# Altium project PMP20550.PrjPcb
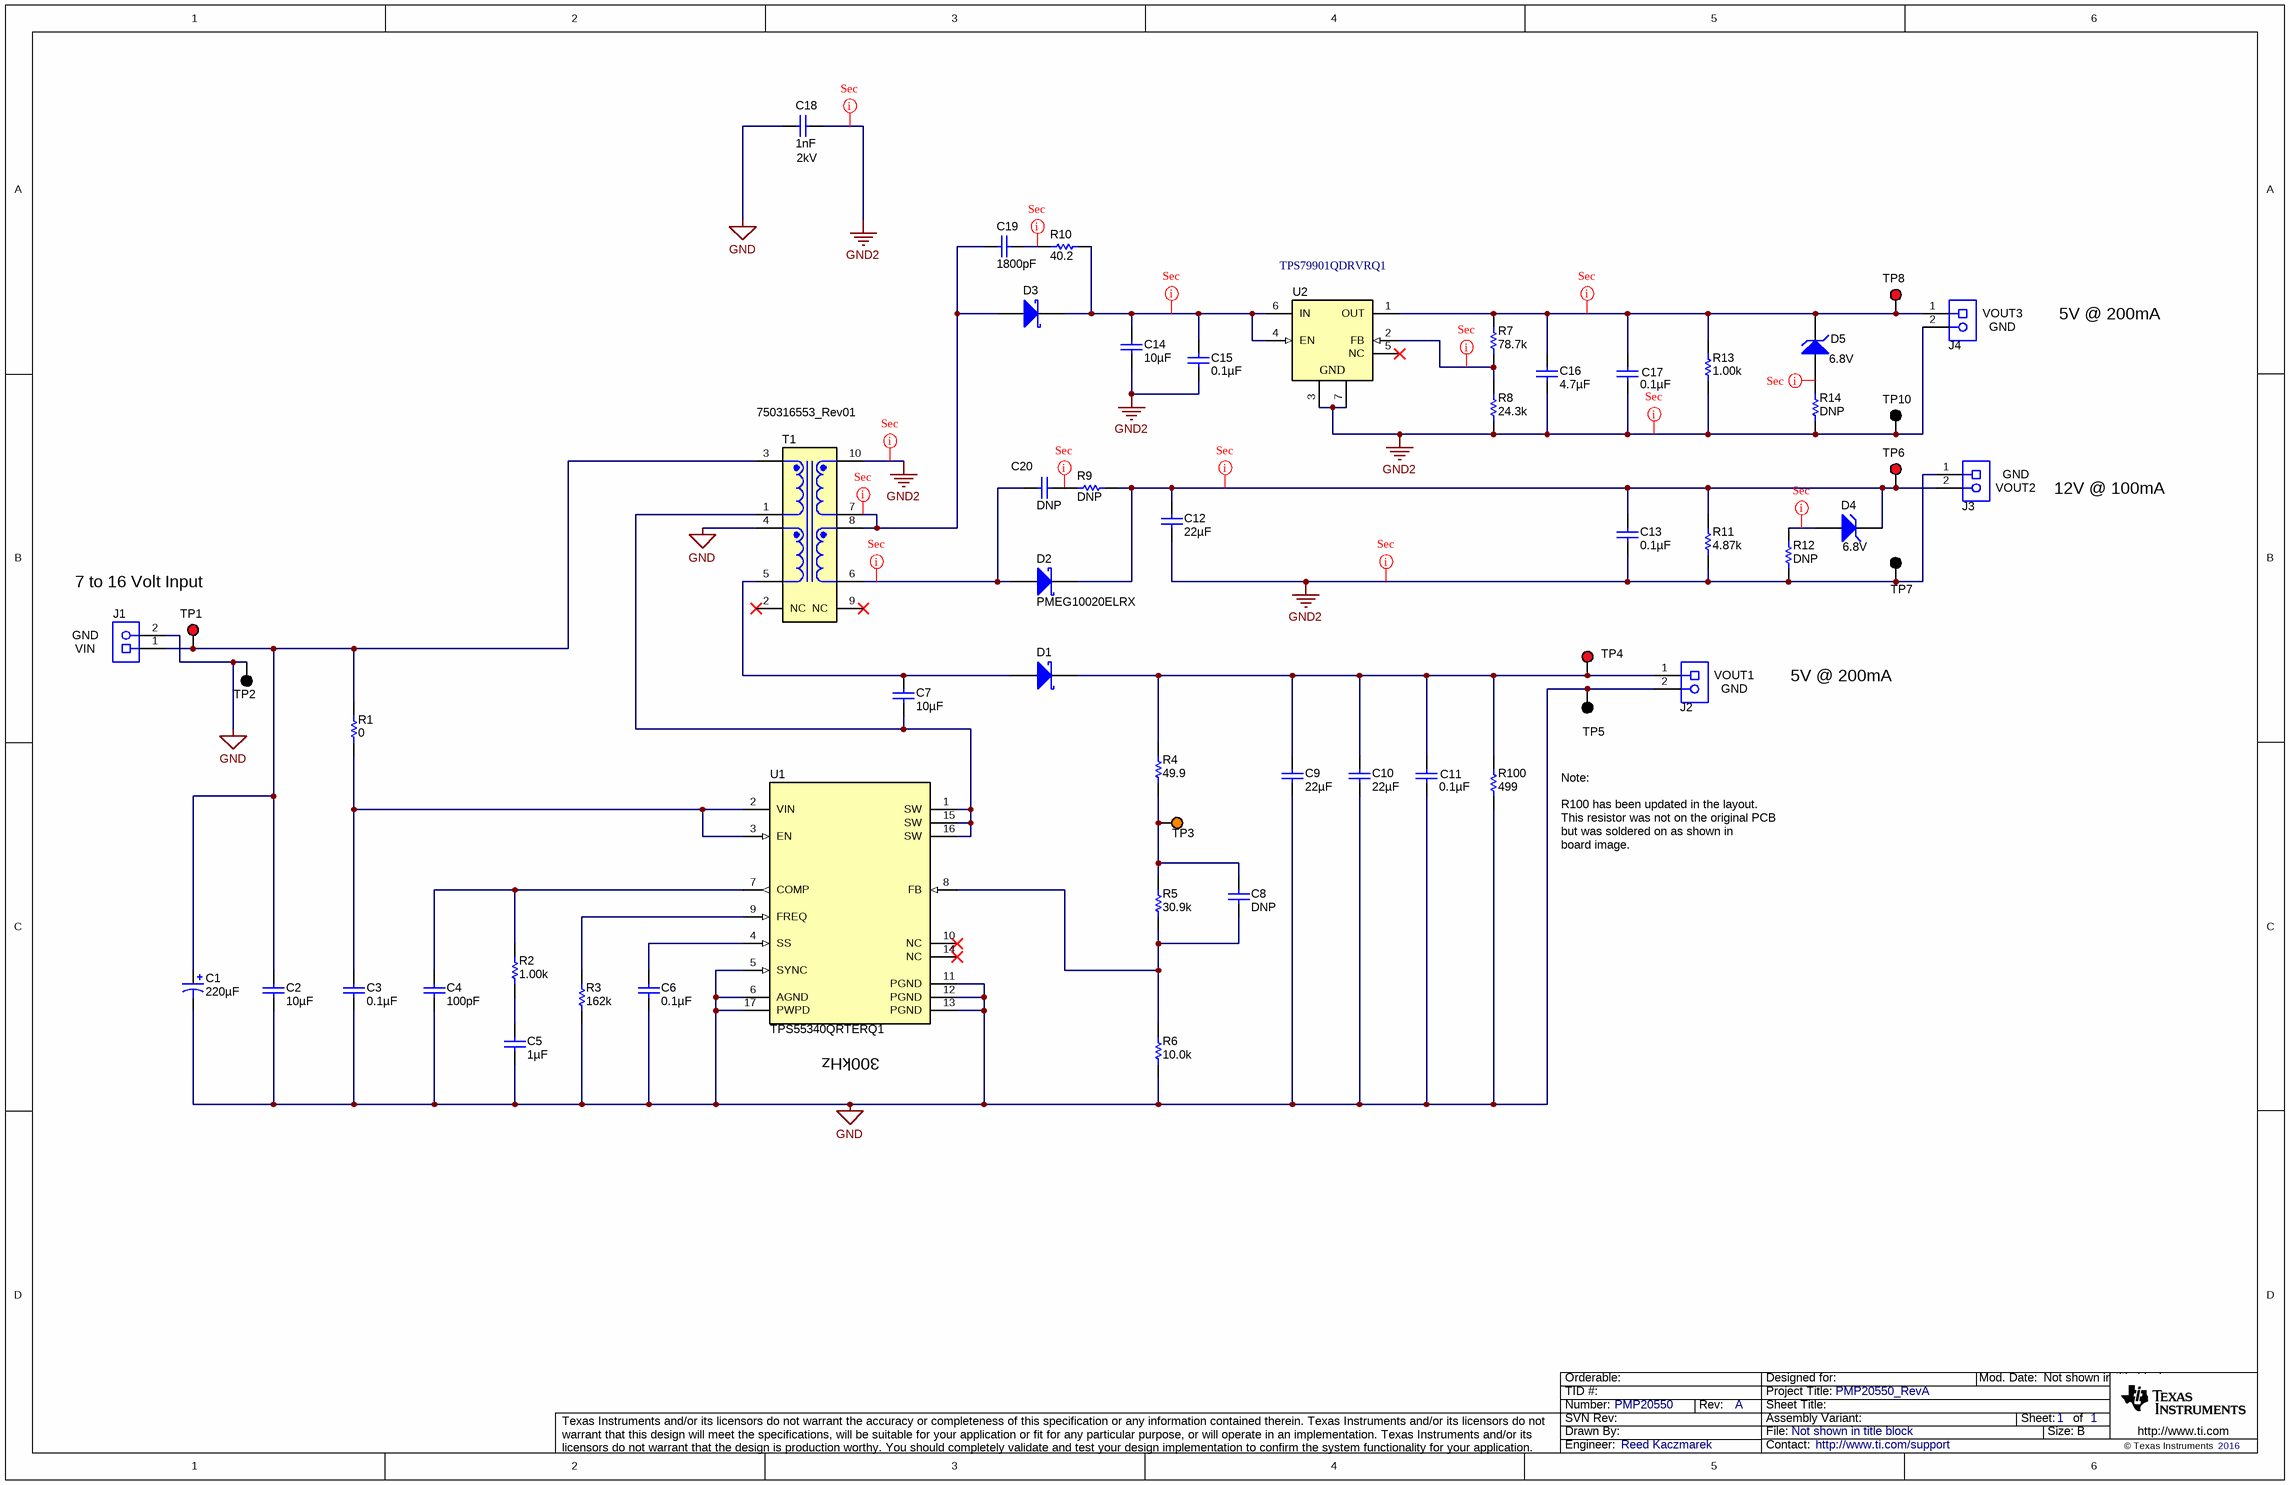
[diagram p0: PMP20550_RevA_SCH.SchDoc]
TechSupport: http://www.ti.com/support; SCH_Rev: A; PRJ_Title: PMP20550_RevA; PRJ_Number: PMP20550; PRJ_Engineer: Reed Kaczmarek; PCB_Rev: A; CopyrightYear: 2016
1 sheet, 56 parts. Net scope: global (net labels, ports and power ports of the same name join across sheets).
Board file: PMP20550_RevA.PcbDoc

## Sheet PMP20550_RevA_SCH.SchDoc
size 431 x 279 mm; Date: Not shown in title block; ApprovedBy: Not shown in title block; CheckedBy: Not shown in title block; Author: Not shown in title block; CompanyName: Not shown in title block; Engineer: Not shown in title block; Organization: Not shown in title block; Address1: Not shown in title block; Address2: Not shown in title block; Address3: Not shown in title block; Address4: Not shown in title block; DocumentNumber: 1; Revision: Use project parameter SCH_Rev; SheetNumber: 1; SheetTotal: 1; PageSetup: Record=PageOptions¦CenterHorizontal=True¦CenterVertical=True¦PrintScale=1.00¦XCorrection=1.00¦YCorrection=1.00¦PrintKind=0¦BorderSize=5000000¦LeftOffset=0¦BottomOffset=0¦Orientation=2¦PaperLength=1000¦PaperWidth=1000¦Scale=100¦PaperSource=15¦PrintQuality=600¦MediaType=1¦DitherType=10¦PaperKind=Letter¦PrintScaleMode=1

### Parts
C1  ValueDisplayed: 220µF  [SM_RADIAL_G]  (hidden comment: EEE-FC1V221P)
C2  ValueDisplayed: 10µF  [1206]  (hidden comment: GMK316AB7106KL)
C3  ValueDisplayed: 0.1µF  [0603]  (hidden comment: C1608X7R1E104K080AA)
C4  ValueDisplayed: 100pF  [0603]  (hidden comment: CGA3E2NP01H101J080AA)
C5  ValueDisplayed: 1µF  [0603]  (hidden comment: UMK107AB7105KA-T)
C6  ValueDisplayed: 0.1µF  [0603]  (hidden comment: C1608X7R1E104K080AA)
C7  ValueDisplayed: 10µF  [0805_HV]  (hidden comment: GRM21BR6YA106KE43L)
C8  ValueDisplayed: DNP  [0402]  (hidden comment: GRM1555C1H201JA01D)
C9  ValueDisplayed: 22µF  [0805_HV]  (hidden comment: GRM21BZ71A226ME15L)
C10  ValueDisplayed: 22µF  [0805_HV]  (hidden comment: GRM21BZ71A226ME15L)
C11  ValueDisplayed: 0.1µF  [0603]  (hidden comment: C0603X104K8RACTU)
C12  ValueDisplayed: 22µF  [1210_280]  (hidden comment: 12103D226MAT2A)
C13  ValueDisplayed: 0.1µF  [0603]  (hidden comment: GRM188R71H104KA93D)
C14  ValueDisplayed: 10µF  [0603]  (hidden comment: GRM188Z71A106MA73D)
C15  ValueDisplayed: 0.1µF  [0603]  (hidden comment: C1608X7R1E104K080AA)
C16  ValueDisplayed: 4.7µF  [0805_HV]  (hidden comment: C2012X7R1E474K125AA)
C17  ValueDisplayed: 0.1µF  [0603]  (hidden comment: C0603X104K8RACTU)
C18  ValueDisplayed: 1nF  Value2: 2kV  [1812]  (hidden comment: GR443QR73D102KW01L)
C19  ValueDisplayed: 1800pF  [0603]  (hidden comment: GRM1885C1H182JA01D)
C20  ValueDisplayed: DNP  [0603]  (hidden comment: GRM1885C1H111JA01D)
D1  PMEG2020EJ,115  [SOD-323F]  (value not drawn)
D2  PMEG10020ELRX  [SOD-123W]
D3  PMEG2020EJ,115  [SOD-323F]  (value not drawn)
D4  value 6.8V  [SOD-323]  (hidden comment: MMSZ5235BS-7-F)
D5  value 6.8V  [SOD-323]  (hidden comment: MMSZ5235BS-7-F)
J1  1984617  [Phoenix_1984617]  (value not drawn)
J2  1984617  [Phoenix_1984617]  (value not drawn)
J3  1984617  [Phoenix_1984617]  (value not drawn)
J4  1984617  [Phoenix_1984617]  (value not drawn)
R1  ValueDisplayed: 0  [0603]  (hidden comment: ERJ-3GEY0R00V)
R2  ValueDisplayed: 1.00k  [0603]  (hidden comment: RT0603BRB071KL)
R3  ValueDisplayed: 162k  [0603]  (hidden comment: CRCW0603162KFKEA)
R4  ValueDisplayed: 49.9  [0402]  (hidden comment: ERJ-2RKF49R9X)
R5  ValueDisplayed: 30.9k  [0603]  (hidden comment: CRCW060330K9FKEA)
R6  ValueDisplayed: 10.0k  [0402]  (hidden comment: ERJ-2RKF1002X)
R7  ValueDisplayed: 78.7k  [0603]  (hidden comment: RC0603FR-0778K7L)
R8  ValueDisplayed: 24.3k  [0603]  (hidden comment: RT0603DRE0724K3L)
R9  ValueDisplayed: DNP  [0603]  (hidden comment: CPF0603B1K62E)
R10  ValueDisplayed: 40.2  [0603]  (hidden comment: CRCW060340R2FKEA)
R11  ValueDisplayed: 4.87k  [0805_HV]  (hidden comment: ERJ-6ENF4871V)
R12  ValueDisplayed: DNP  [0603]  (hidden comment: CPF0603B1K62E)
R13  ValueDisplayed: 1.00k  [0805_HV]  (hidden comment: RT0805BRD071KL)
R14  ValueDisplayed: DNP  [0603]  (hidden comment: CPF0603B1K62E)
R100  ValueDisplayed: 499  [0805_HV]  (hidden comment: RT0805BRD07499RL)
T1  750316553_Rev01  [Wurth_750316553]
TP1  5000  [Keystone5000]  (value not drawn)
TP2  5001  [Keystone5001]  (value not drawn)
TP3  5003  [Keystone5003]  (value not drawn)
TP4  VBUS  [Keystone5000]  (value not drawn)
TP5  5001  [Keystone5001]  (value not drawn)
TP6  5000  [Keystone5000]  (value not drawn)
TP7  5001  [Keystone5001]  (value not drawn)
TP8  5000  [Keystone5000]  (value not drawn)
TP10  5001  [Keystone5001]  (value not drawn)
U1  TPS55340QRTERQ1  [RTE0016C]
U2  TPS79901QDRVRQ1  [DRV0006A]

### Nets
GND: C1.2(-) C2.2 C3.2 C4.2 C5.2 C6.2 C9.2 C10.2 C11.2 C18.2 J1.2 J2.2 R3.1 R6.1 R100.1 T1.4 TP2.1 TP5.1 U1.5(SYNC) U1.6(AGND) U1.11(PGND) U1.12(PGND) U1.13(PGND) U1.17(PWPD)
GND2: C12.2 C13.2 C14.2 C15.2 C16.2 C17.2 C18.1 J3.1 J4.2 R8.1 R11.1 R12.2 R13.1 R14.2 T1.10 TP7.1 TP10.1 U2.3(GND) U2.7(GND)
NetC1_1: C1.1(+) C2.1 J1.1 R1.2 T1.3 TP1.1
NetC3_1: C3.1 R1.1 U1.2(VIN) U1.3(EN)
NetC4_1: C4.1 R2.2 U1.7(COMP)
NetC5_1: C5.1 R2.1
NetC6_1: C6.1 U1.4(SS)
NetC7_1: C7.1 D1.2(A) T1.5
NetC7_2: C7.2 T1.1 U1.1(SW) U1.15(SW) U1.16(SW)
NetC8_1: C8.1 R4.1 R5.2 TP3.1
NetC8_2: C8.2 R5.1 R6.2 U1.8(FB)
NetC9_1: C9.1 C10.1 C11.1 D1.1(K) J2.1 R4.2 R100.2 TP4.1
NetC12_1: C12.1 C13.1 D2.1(K) D4.1(K) J3.2 R9.1 R11.2 TP6.1
NetC14_1: C14.1 C15.1 D3.1(K) R10.2 U2.4(EN) U2.6(IN)
NetC16_1: C16.1 C17.1 D5.1(K) J4.1 R7.2 R13.2 TP8.1 U2.1(OUT)
NetC19_1: C19.1 R10.1
NetC19_2: C19.2 D3.2(A) T1.7 T1.8
NetC20_1: C20.1 R9.2
NetC20_2: C20.2 D2.2(A) T1.6
NetD4_2: D4.2(A) R12.1
NetD5_2: D5.2(A) R14.1
NetR3_2: R3.2 U1.9(FREQ)
NetR7_1: R7.1 R8.2 U2.2(FB)

Not connected (* = marked no-connect by the designer): T1 2(NC)* 9(NC)*; U1 10(NC)* 14(NC)*; U2 5(NC)*

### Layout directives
net class Undefined: GND2, NetC12_1, NetC14_1, NetC16_1, NetC19_1, NetC19_2, NetC20_1, NetC20_2, NetD4_2, NetD5_2, NetR7_1

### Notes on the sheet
- (near J4) VOUT3
- (near J4) GND
- 5V @ 200mA
- (near J3) VOUT2
- (near J3) GND
- 12V @ 100mA
- (near J1) GND
- 7 to 16 Volt Input
- (near J1) VIN
- (near J2) VOUT1
- (near J2) GND
- Note:
  R100 has been updated in the layout.
  This resistor was not on the original PCB
  but was soldered on as shown in
  board image.
- (near U1) 300kHz

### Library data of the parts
C1 = EEE-FC1V221P: CAP, AL, 220 µF, 35 V, +/- 20%, 0.15 ohm, SMD; Manufacturer: Panasonic; Polarized: Y; CompType: Capacitor; Value: 220uF; U/M: EA; Cap_F: 0.00022; Tolerance_%: 20; VDC_V: 35; Value2: 35V; ESR_ohm: 0.15; IRMS_A: 0.67; TaMin_C: -40; TaMax_C: 105; Cap_Case: G; SizeAreaWB_mm2: 172.2; SizeArea_mm2: 123.6; SizeX_mm: 12; SizeY_mm: 10.3; SizeZ_mm: 10.2; AEC Category: Q200
C2 = GMK316AB7106KL: CAP, CERM, 10 µF, 35 V, +/- 10%, X7R, 1206; Manufacturer: Taiyo Yuden; Polarized: N; CompType: Capacitor; Value: 10uF; U/M: EA; Cap_F: 0.00001; Tolerance_%: 10; Value1: Unknown; VDC_V: 35; Value2: 35V; TaMin_C: -55; TaMax_C: 125; SizeArea_mm2: 5.12; SizeAreaWB_mm2: 10.92; SizeX_mm: 3.2; SizeY_mm: 1.6; SizeZ_mm: 1.35; AEC Category: Q200
C3 C6 C15 = C1608X7R1E104K080AA: CAP, CERM, 0.1 µF, 25 V, +/- 10%, X7R, 0603; Manufacturer: TDK; Polarized: N; CompType: Capacitor; Value: 0.1uF; U/M: EA; Cap_F: 0.0000001; Tolerance_%: 10; Value1: Unknown; VDC_V: 25; Value2: 25V; TaMin_C: -55; TaMax_C: 125; SizeArea_mm2: 1.28; SizeAreaWB_mm2: 4.68; SizeX_mm: 1.6; SizeY_mm: 0.8; SizeZ_mm: 1; AEC Category: Q200
C4 = CGA3E2NP01H101J080AA: CAP, CERM, 100 pF, 50 V, +/- 5%, C0G/NP0, AEC-Q200 Grade 0, 0603; Manufacturer: TDK; Polarized: N; CompType: Capacitor; Value: 100pF; U/M: EA; Cap_F: 0.0000000001; Tolerance_%: 5; Value1: Unknown; VDC_V: 50; Value2: 50V; TaMin_C: -55; TaMax_C: 150; SizeArea_mm2: 1.28; SizeAreaWB_mm2: 4.68; SizeX_mm: 1.6; SizeY_mm: 0.8; SizeZ_mm: 1; AEC Category: Q200; AEC Qualified: Y; AEC Grade: 0
C5 = UMK107AB7105KA-T: CAP, CERM, 1 µF, 50 V, +/- 10%, X7R, 0603; Manufacturer: Taiyo Yuden; Polarized: N; CompType: Capacitor; Value: 1uF; U/M: EA; Cap_F: 0.000001; Tolerance_%: 10; Value1: Unknown; VDC_V: 50; Value2: 50V; TaMin_C: -55; TaMax_C: 125; SizeArea_mm2: 1.28; SizeAreaWB_mm2: 4.68; SizeX_mm: 1.6; SizeY_mm: 0.8; SizeZ_mm: 1; AEC Category: Q200
C7 = GRM21BR6YA106KE43L: CAP, CERM, 10 µF, 35 V, +/- 10%, X5R, 0805; Manufacturer: MuRata; Polarized: N; CompType: Capacitor; Value: 10uF; U/M: EA; Cap_F: 0.00001; Tolerance_%: 10; Value1: Unknown; VDC_V: 35; Value2: 35V; TaMin_C: -55; TaMax_C: 85; Cap_Case: 0805; SizeArea_mm2: 2.5; SizeAreaWB_mm2: 6.75; SizeX_mm: 2; SizeY_mm: 1.25; SizeZ_mm: 1.45; AEC Category: Q200
C8 = GRM1555C1H201JA01D: CAP, CERM, 200 pF, 50 V, +/- 5%, C0G/NP0, 0402; Manufacturer: MuRata; Polarized: N; CompType: Capacitor; Value: 200pF; U/M: EA; Cap_F: 0.0000000002; Tolerance_%: 5; Value1: Unknown; VDC_V: 50; Value2: 50V; TaMin_C: -55; TaMax_C: 125; SizeArea_mm2: 0.5; SizeAreaWB_mm2: 3; SizeX_mm: 1; SizeZ_mm: 0.6; AEC Category: Q200
C9 C10 = GRM21BZ71A226ME15L: CAP, CERM, 22 µF, 10 V, +/- 20%, X7R, 0805; Manufacturer: MuRata; Polarized: N; CompType: Capacitor; Value: 22uF; U/M: EA; Cap_F: 0.000022; Tolerance_%: 20; Value1: Unknown; VDC_V: 10; Value2: 10V; TaMin_C: -55; TaMax_C: 125; Cap_Case: 0805; SizeArea_mm2: 2.5; SizeAreaWB_mm2: 6.75; SizeX_mm: 2; SizeY_mm: 1.25; SizeZ_mm: 1.45; AEC Category: Q200
C11 C17 = C0603X104K8RACTU: CAP, CERM, 0.1 µF, 10 V, +/- 10%, X7R, 0603; Manufacturer: Kemet; Polarized: N; CompType: Capacitor; Value: 0.1uF; U/M: EA; Cap_F: 0.0000001; Tolerance_%: 10; Value1: Unknown; Value2: 10V; TaMin_C: -55; TaMax_C: 125; SizeArea_mm2: 1.28; SizeAreaWB_mm2: 4.68; SizeX_mm: 1.6; SizeY_mm: 0.8; SizeZ_mm: 1; AEC Category: Q200
C12 = 12103D226MAT2A: CAP, CERM, 22 µF, 25 V, +/- 20%, X5R, 1210; Manufacturer: AVX; Polarized: N; CompType: Capacitor; Value: 22uF; U/M: EA; Cap_F: 0.000022; Tolerance_%: 20; Value1: Unknown; VDC_V: 25; Value2: 25V; TaMin_C: -55; TaMax_C: 85; Cap_Case: 1210; SizeArea_mm2: 8; SizeAreaWB_mm2: 14.7; SizeX_mm: 3.2; SizeY_mm: 2.5; SizeZ_mm: 2.8; AEC Category: Q200
C13 = GRM188R71H104KA93D: CAP, CERM, 0.1 µF, 50 V, +/- 10%, X7R, 0603; Manufacturer: MuRata; Polarized: N; CompType: Capacitor; Value: 0.1uF; U/M: EA; Cap_F: 0.0000001; Tolerance_%: 10; Value1: Unknown; VDC_V: 50; Value2: 50V; TaMin_C: -55; TaMax_C: 125; SizeArea_mm2: 1.28; SizeAreaWB_mm2: 4.68; SizeX_mm: 1.6; SizeY_mm: 0.8; SizeZ_mm: 1; AEC Category: Q200
C14 = GRM188Z71A106MA73D: CAP, CERM, 10 µF, 10 V, +/- 20%, X7R, 0603; Manufacturer: MuRata; Polarized: N; CompType: Capacitor; Value: 10uF; U/M: EA; Cap_F: 0.00001; Tolerance_%: 20; Value1: Unknown; VDC_V: 10; Value2: 10V; TaMin_C: -55; TaMax_C: 125; SizeArea_mm2: 1.28; SizeAreaWB_mm2: 4.68; SizeX_mm: 1.6; SizeY_mm: 0.8; SizeZ_mm: 1; AEC Category: Q200
C16 = C2012X7R1E474K125AA: CAP, CERM, 4.7 µF, 25 V, +/- 10%, X7R, 0805; Manufacturer: TDK; Polarized: N; CompType: Capacitor; Value: 4.7uF; U/M: EA; Cap_F: 0.0000047; Tolerance_%: 10; Value1: Unknown; VDC_V: 25; Value2: 25V; TaMin_C: -55; TaMax_C: 125; Cap_Case: 0805; SizeArea_mm2: 2.5; SizeAreaWB_mm2: 6.75; SizeX_mm: 2; SizeY_mm: 1.25; SizeZ_mm: 1.45; AEC Category: Q200
C18 = GR443QR73D102KW01L: CAP, CERM, 1000 pF, 2000 V, +/- 10%, X7R, 1812; Manufacturer: MuRata; Polarized: N; CompType: Capacitor; Value: 1000pF; U/M: EA; Cap_F: 0.000000001; Tolerance_%: 10; Value1: Unknown; VDC_V: 2000; TaMin_C: -55; TaMax_C: 125; SizeArea_mm2: 14.4; SizeAreaWB_mm2: 23.1; SizeX_mm: 4.5; SizeY_mm: 3.2; SizeZ_mm: 1.35; AEC Category: Q200
C19 = GRM1885C1H182JA01D: CAP, CERM, 1800 pF, 50 V, +/- 5%, C0G/NP0, 0603; Manufacturer: MuRata; Polarized: N; CompType: Capacitor; Value: 1800pF; U/M: EA; Cap_F: 0.0000000018; Tolerance_%: 5; Value1: Unknown; VDC_V: 50; Value2: 50V; TaMin_C: -55; TaMax_C: 125; SizeArea_mm2: 1.28; SizeAreaWB_mm2: 4.68; SizeX_mm: 1.6; SizeY_mm: 0.8; SizeZ_mm: 1; AEC Category: Q200
C20 = GRM1885C1H111JA01D: CAP, CERM, 110 pF, 50 V, +/- 5%, C0G/NP0, 0603; Manufacturer: MuRata; Polarized: N; CompType: Capacitor; Value: 110pF; U/M: EA; Cap_F: 0.00000000011; Tolerance_%: 5; Value1: Unknown; VDC_V: 50; Value2: 50V; TaMin_C: -55; TaMax_C: 125; SizeArea_mm2: 1.28; SizeAreaWB_mm2: 4.68; SizeX_mm: 1.6; SizeY_mm: 0.8; SizeZ_mm: 1; AEC Category: Q200
D1 D3 = PMEG2020EJ,115: Diode, Schottky, 20 V, 2 A, SOD-323F; Manufacturer: NXP Semiconductor; U/M: EA; Vf_V: 0.525; Value: 20V; Value1: 2A; Value2: 0.525V; Io_A: 2; Vr_V: 20; TJmax_C: 150; SizeAreaWB_mm2: 7.875; SizeArea_mm2: 3.125; SizeX_mm: 2.5; SizeY_mm: 1.25; SizeZ_mm: 0.8; AEC Category: Q101; AEC Qualified: N
D2 = PMEG10020ELRX: Diode, Schottky, 100 V, 2 A, AEC-Q101, SOD-123W; Manufacturer: NXP Semiconductor; U/M: EA; Vf_V: 0.83; Value: 100V; Value1: 2A; Value2: 0.83V; Io_A: 2; Vr_V: 100; TJmax_C: 175; SizeAreaWB_mm2: 12.15; SizeArea_mm2: 5.95; SizeX_mm: 3.5; SizeY_mm: 1.7; SizeZ_mm: 1; AEC Category: Q101; AEC Qualified: Y
D4 D5 = MMSZ5235BS-7-F: Diode, Zener, 6.8 V, 200 mW, SOD-323; Manufacturer: Diodes Inc.; SymbolCreator: a0412235; U/M: EA; Power_W: 0.2; Vz_V: 6.8; Value1: 0.2W; RJA_CperW: 350; SizeAreaWB_mm2: 8.695; SizeArea_mm2: 3.645; SizeX_mm: 2.7; SizeY_mm: 1.35; SizeZ_mm: 1; AEC Category: Q101
J1-J4 = 1984617: Terminal Block, 3.5mm, 2x1, TH; Manufacturer: Phoenix Contact; SymbolCreator: a0412235; Pitch_mm: 3.5; Gender: Female; Row_Count: 1; Current_A: 17.5; Voltage_V: 200; Cert_UL: Y
R1 = ERJ-3GEY0R00V: RES, 0, 5%, 0.1 W, 0603; Manufacturer: Panasonic; CompType: Resistor; Value: 0; Value_Code: 0000; Tolerance_%: 5; Power_W: 0.1; Value2: 0.1W; VDC_V: 50; TempCo: 600 ppm/C; SizeArea_mm2: 1.28; SizeX_mm: 1.6; SizeY_mm: 0.8; SizeZ_mm: 1; EIA_Code: E24; U/M: EA; AEC Category: Q200
R2 = RT0603BRB071KL: RES, 1.00 k, 0.1%, 0.1 W, 0603; Manufacturer: Yageo America; CompType: Resistor; Value: 1.00k; Res_ohm: 1000; Value_Code: 1k00; Tolerance_%: 0.1; Value2: 0.1W; VDC_V: 75; TempCo: 10 ppm/C; SizeArea_mm2: 1.28; SizeX_mm: 1.6; SizeY_mm: 0.8; SizeZ_mm: 1; EIA_Code: E192; U/M: EA; AEC Category: Q200; AEC Qualified: N
R3 = CRCW0603162KFKEA: RES, 162 k, 1%, 0.1 W, 0603; Manufacturer: Vishay-Dale; CompType: Resistor; Value: 162k; Res_ohm: 162000; Tolerance_%: 1; Power_W: 0.1; Value2: 0.1W; VDC_V: 75; TempCo: 100 ppm/C; SizeArea_mm2: 1.28; SizeX_mm: 1.6; SizeY_mm: 0.8; EIA_Code: E96; U/M: EA; AEC Category: Q200
R4 = ERJ-2RKF49R9X: RES, 49.9, 1%, 0.1 W, AEC-Q200 Grade 0, 0402; Manufacturer: Panasonic; CompType: Resistor; Value: 49.9; Value_Code: 49R9; Tolerance_%: 1; Power_W: 0.1; Value2: 0.1W; VDC_V: 50; TempCo: 100 ppm/C; SizeArea_mm2: 0.5; SizeZ_mm: 0.6; EIA_Code: E96; U/M: EA; AEC Category: Q200; AEC Qualified: Y; AEC Grade: 0
R5 = CRCW060330K9FKEA: RES, 30.9 k, 1%, 0.1 W, 0603; Manufacturer: Vishay-Dale; CompType: Resistor; Value: 30.9k; Res_ohm: 30900; Value_Code: 30k9; Tolerance_%: 1; Power_W: 0.1; Value2: 0.1W; VDC_V: 75; TempCo: 100 ppm/C; SizeArea_mm2: 1.28; SizeX_mm: 1.6; SizeY_mm: 0.8; EIA_Code: E96; U/M: EA; AEC Category: Q200
R6 = ERJ-2RKF1002X: RES, 10.0 k, 1%, 0.1 W, 0402; Manufacturer: Panasonic; CompType: Resistor; Value: 10.0k; Res_ohm: 10000; Value_Code: 10k0; Tolerance_%: 1; Power_W: 0.1; Value2: 0.1W; VDC_V: 50; TempCo: 100 ppm/C; SizeArea_mm2: 0.5; SizeZ_mm: 0.6; EIA_Code: E96; U/M: EA; AEC Category: Q200
R7 = RC0603FR-0778K7L: RES, 78.7 k, 1%, 0.1 W, 0603; Manufacturer: Yageo America; CompType: Resistor; Value: 78.7k; Res_ohm: 78700; Value_Code: 78k7; Tolerance_%: 1; Power_W: 0.1; Value2: 0.1W; VDC_V: 150; TempCo: 200 ppm/C; SizeArea_mm2: 1.28; SizeX_mm: 1.6; SizeY_mm: 0.8; EIA_Code: E96; U/M: EA; AEC Category: Q200
R8 = RT0603DRE0724K3L: RES, 24.3 k, 0.5%, 0.1 W, 0603; Manufacturer: Yageo America; CompType: Resistor; Value: 24.3k; Res_ohm: 24300; Value_Code: 24k3; Tolerance_%: 0.5; Power_W: 0.1; Value2: 0.1W; VDC_V: 75; TempCo: 50 ppm/C; SizeArea_mm2: 1.28; SizeX_mm: 1.6; SizeY_mm: 0.8; SizeZ_mm: 1; EIA_Code: E192; U/M: EA; AEC Category: Q200
R9 R12 R14 = CPF0603B1K62E: RES, 1.62 k, 0.1%, 0.063 W, 0603; Manufacturer: TE Connectivity; CompType: Resistor; Value: 1.62k; Res_ohm: 1620; Value_Code: 1k62; Tolerance_%: 0.1; Power_W: 0.063; Value2: 0.063W; VDC_V: 50; TempCo: 25 ppm/C; SizeArea_mm2: 1.28; SizeX_mm: 1.6; SizeY_mm: 0.8; SizeZ_mm: 1; EIA_Code: E192; U/M: EA; AEC Category: Q200
R10 = CRCW060340R2FKEA: RES, 40.2, 1%, 0.1 W, 0603; Manufacturer: Vishay-Dale; CompType: Resistor; Value: 40.2; Value_Code: 40R2; Tolerance_%: 1; Power_W: 0.1; Value2: 0.1W; VDC_V: 75; TempCo: 100 ppm/C; SizeArea_mm2: 1.28; SizeX_mm: 1.6; SizeY_mm: 0.8; EIA_Code: E96; U/M: EA; AEC Category: Q200
R11 = ERJ-6ENF4871V: RES, 4.87 k, 1%, 0.125 W, 0805; Manufacturer: Panasonic; CompType: Resistor; Value: 4.87k; Res_ohm: 4870; Value_Code: 4k87; Tolerance_%: 1; Power_W: 0.125; Value2: 0.125W; TempCo: 100 ppm/C; SizeArea_mm2: 2.5; SizeX_mm: 2; SizeY_mm: 1.25; SizeZ_mm: 1.45; EIA_Code: E96; U/M: EA; AEC Category: Q200
R13 = RT0805BRD071KL: RES, 1.00 k, 0.1%, 0.125 W, 0805; Manufacturer: Yageo America; CompType: Resistor; Value: 1.00k; Res_ohm: 1000; Value_Code: 1k00; Tolerance_%: 0.1; Power_W: 0.125; Value2: 0.125W; VDC_V: 150; TempCo: 25 ppm/C; SizeArea_mm2: 2.5; SizeX_mm: 2; SizeY_mm: 1.25; SizeZ_mm: 1.45; EIA_Code: E192; U/M: EA; AEC Category: Q200
R100 = RT0805BRD07499RL: RES, 499, 0.1%, 0.125 W, 0805; Manufacturer: Yageo America; CompType: Resistor; Value: 499; Value_Code: 499R; Tolerance_%: 0.1; Power_W: 0.125; Value2: 0.125W; VDC_V: 150; TempCo: 25 ppm/C; SizeArea_mm2: 2.5; SizeX_mm: 2; SizeY_mm: 1.25; SizeZ_mm: 1.45; EIA_Code: E192; U/M: EA; AEC Category: Q200
T1 = 750316553: Transformer, 52 uH, SMT; Manufacturer: Wurth Elektronik; SymbolCreator: Altium; Lp: 52; DCR_ohm: 0.065; Ns1toNp: 1.19; Ns2toNp: 1.13; Rs1: 0.09; Rs2: 0.085; SizeAreaWB_mm2: 305.335; SizeArea_mm2: 238.915; SizeX_mm: 17.75; SizeY_mm: 13.46; SizeZ_mm: 12.7
TP1 TP6 TP8 = 5000: Test Point, Miniature, Red, TH; Manufacturer: Keystone; CompType: Test Point Loop; ContactFinish: Silver
TP2 TP5 TP7 TP10 = 5001: Test Point, Miniature, Black, TH; Manufacturer: Keystone; CompType: Test Point Loop; ContactFinish: Silver
TP3 = 5003: Test Point, Miniature, Orange, TH; Manufacturer: Keystone; CompType: Test Point Loop; ContactFinish: Silver
TP4 = 5000: Test Point, TH, Miniature, Red; Manufacturer: Keystone; CompType: Test Point Loop; U/M: EA
U1 = TPS55340QRTERQ1: Integrated 5-A 40-V Wide Input Range Boost/SEPIC/Flyback DC-DC Regulator, RTE0016C; Alternate PartNumber: TPS55340QRTETQ1; Manufacturer: Texas Instruments; SymbolCreator: x0208326; SizeArea_mm2: 9; SizeAreaWB_mm2: 16; SizeX_mm: 3; SizeZ_mm: 0.8; CompType: IC; U/M: EA
U2 = TPS79901QDRVRQ1: Single Output High PSRR LDO, 200 mA, Adjustable 1.2 to 6.5 V Output, 2.7 to 6.5 V Input, with Low IQ, 6-pin SON (DRV), -40 to 125 degC, Green (RoHS & no Sb/Br); Manufacturer: Texas Instruments; Alternate PartNumber: Equivalent; Accuracy(%): 2; Iout(Max)(A): 0.2; Iq(Typ)(mA): 0.04; Rating: Automotive; SubFamily: Single Channel LDO; Vdo(Typ)(mV): 90; Vin(Max)(V): 6.5; Vin(Min)(V): 2.7; Vout Adj(Min)(V): 1.2

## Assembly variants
001: not fitted C3 C7 C100 C101 D100 D101 R100 R101 R102 R103 R104 R105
